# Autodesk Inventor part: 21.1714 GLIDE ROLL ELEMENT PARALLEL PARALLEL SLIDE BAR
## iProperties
Created: 2007-05
Part Number: 21.1714 GLIDE ROLL ELEMENT PARALLEL PARALLEL SLIDE BAR
Material: UHMW, Black
Document SubType Name: Modeling
Designer: Andy Moles
Density: 0.94 g/cm^3
Author: Andy Moles
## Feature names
1. Extrusion1
2. Extrusion2
3. Extrusion3
4. Hole1
5. Extrusion4
6. Extrusion5
7. Extrusion6
